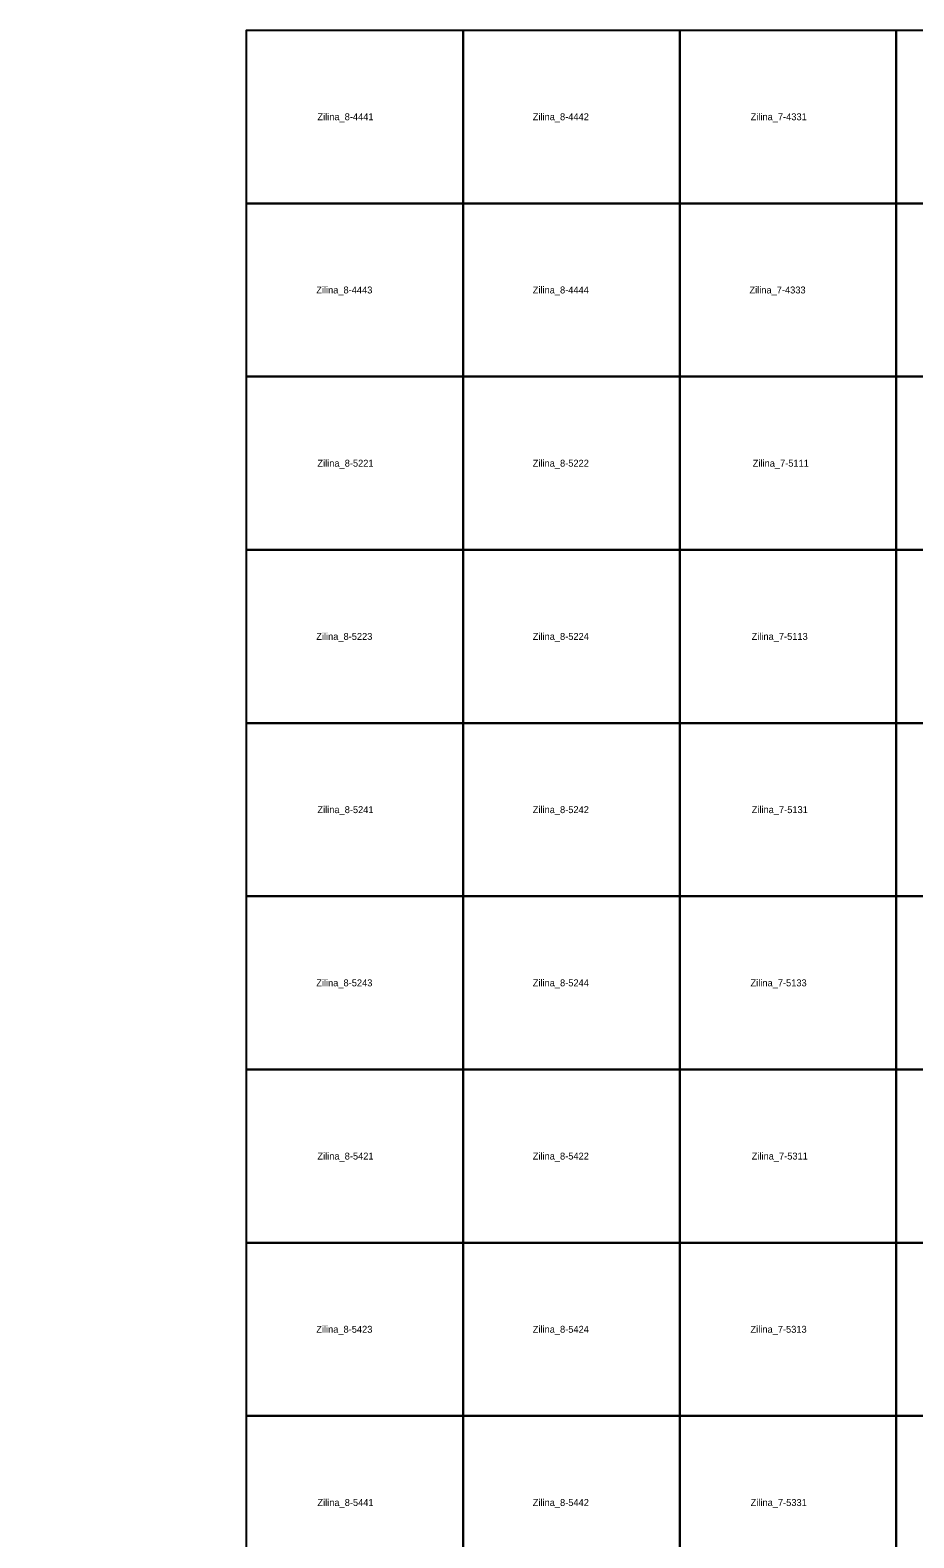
# Model space of a CAD drawing. Extents: x -445938 to -437812, y -1177250 to -1169500.
# Drawn here: x -445938 to -444662, y -1171676 to -1169500 of the extents above; entities that cross this region are included whole.
import ezdxf

# ---------------------------------------------------------------- set-up
doc = ezdxf.new("R2010")
doc.units = 0
for name, color, linetype in [('Vrstva 1', 7, 'Continuous'), ('Vrstva 4', 7, 'Continuous'), ('Vrstva 6', 7, 'Continuous')]:
    doc.layers.add(name, color=color, linetype=linetype)

msp = doc.modelspace()

# ---------------------------------------------------------------- linework, layer by layer
at = {"layer": 'Vrstva 1'}
msp.add_lwpolyline([(-440625, -1175500), (-441562.5, -1175500), (-441562.5, -1175000), (-442812.5, -1175000), (-442812.5, -1175750), (-443437.5, -1175750), (-443437.5, -1177250), (-445000, -1177250), (-445000, -1175500), (-445312.5, -1175500), (-445312.5, -1173750), (-445937.5, -1173750), (-445937.5, -1172250), (-445625, -1172250), (-445625, -1169500), (-444062.5, -1169500), (-444062.5, -1169750), (-441562.5, -1169750), (-441562.5, -1170000), (-440000, -1170000)], dxfattribs=at)
at = {"layer": 'Vrstva 4'}
for points in [[(-445312.5, -1169500), (-445312.5, -1169750), (-445625, -1169750), (-445625, -1169500)], [(-445000, -1169500), (-445000, -1169750), (-445312.5, -1169750), (-445312.5, -1169500)], [(-444687.5, -1169500), (-444687.5, -1169750), (-445000, -1169750), (-445000, -1169500)], [(-444375, -1169500), (-444375, -1169750), (-444687.5, -1169750), (-444687.5, -1169500)], [(-445312.5, -1169750), (-445312.5, -1170000), (-445625, -1170000), (-445625, -1169750)], [(-445000, -1169750), (-445000, -1170000), (-445312.5, -1170000), (-445312.5, -1169750)], [(-444687.5, -1169750), (-444687.5, -1170000), (-445000, -1170000), (-445000, -1169750)], [(-444375, -1169750), (-444375, -1170000), (-444687.5, -1170000), (-444687.5, -1169750)], [(-445312.5, -1170000), (-445312.5, -1170250), (-445625, -1170250), (-445625, -1170000)], [(-445000, -1170000), (-445000, -1170250), (-445312.5, -1170250), (-445312.5, -1170000)], [(-444687.5, -1170000), (-444687.5, -1170250), (-445000, -1170250), (-445000, -1170000)], [(-444375, -1170000), (-444375, -1170250), (-444687.5, -1170250), (-444687.5, -1170000)], [(-445312.5, -1170250), (-445312.5, -1170500), (-445625, -1170500), (-445625, -1170250)], [(-445000, -1170250), (-445000, -1170500), (-445312.5, -1170500), (-445312.5, -1170250)], [(-444687.5, -1170250), (-444687.5, -1170500), (-445000, -1170500), (-445000, -1170250)], [(-444375, -1170250), (-444375, -1170500), (-444687.5, -1170500), (-444687.5, -1170250)], [(-445312.5, -1170500), (-445312.5, -1170750), (-445625, -1170750), (-445625, -1170500)], [(-445000, -1170500), (-445000, -1170750), (-445312.5, -1170750), (-445312.5, -1170500)], [(-444687.5, -1170500), (-444687.5, -1170750), (-445000, -1170750), (-445000, -1170500)], [(-444375, -1170500), (-444375, -1170750), (-444687.5, -1170750), (-444687.5, -1170500)], [(-445312.5, -1170750), (-445312.5, -1171000), (-445625, -1171000), (-445625, -1170750)], [(-445000, -1170750), (-445000, -1171000), (-445312.5, -1171000), (-445312.5, -1170750)], [(-444687.5, -1170750), (-444687.5, -1171000), (-445000, -1171000), (-445000, -1170750)], [(-444375, -1170750), (-444375, -1171000), (-444687.5, -1171000), (-444687.5, -1170750)], [(-445312.5, -1171000), (-445312.5, -1171250), (-445625, -1171250), (-445625, -1171000)], [(-445000, -1171000), (-445000, -1171250), (-445312.5, -1171250), (-445312.5, -1171000)], [(-444687.5, -1171000), (-444687.5, -1171250), (-445000, -1171250), (-445000, -1171000)], [(-444375, -1171000), (-444375, -1171250), (-444687.5, -1171250), (-444687.5, -1171000)], [(-445312.5, -1171250), (-445312.5, -1171500), (-445625, -1171500), (-445625, -1171250)], [(-445000, -1171250), (-445000, -1171500), (-445312.5, -1171500), (-445312.5, -1171250)], [(-444687.5, -1171250), (-444687.5, -1171500), (-445000, -1171500), (-445000, -1171250)], [(-444375, -1171250), (-444375, -1171500), (-444687.5, -1171500), (-444687.5, -1171250)], [(-445312.5, -1171500), (-445312.5, -1171750), (-445625, -1171750), (-445625, -1171500)], [(-445000, -1171500), (-445000, -1171750), (-445312.5, -1171750), (-445312.5, -1171500)], [(-444687.5, -1171500), (-444687.5, -1171750), (-445000, -1171750), (-445000, -1171500)], [(-444375, -1171500), (-444375, -1171750), (-444687.5, -1171750), (-444687.5, -1171500)]]:
    msp.add_lwpolyline(points, close=True, dxfattribs=at)

# ---------------------------------------------------------------- texts
at = {"layer": 'Vrstva 6'}
for s, p in [('Zilina_8-4441', (-445522.878, -1169630)), ('Zilina_8-4442', (-445212.072, -1169630)), ('Zilina_7-4331', (-444897.564, -1169630)), ('Zilina_8-4443', (-445524.572, -1169880)), ('Zilina_8-4444', (-445212.072, -1169880)), ('Zilina_7-4333', (-444899.256, -1169880)), ('Zilina_8-5221', (-445522.878, -1170130)), ('Zilina_8-5222', (-445212.072, -1170130)), ('Zilina_7-5111', (-444894.494, -1170130)), ('Zilina_8-5223', (-445524.572, -1170380)), ('Zilina_8-5224', (-445212.072, -1170380)), ('Zilina_7-5113', (-444896.186, -1170380)), ('Zilina_8-5241', (-445522.878, -1170630)), ('Zilina_8-5242', (-445212.072, -1170630)), ('Zilina_7-5131', (-444896.028, -1170630)), ('Zilina_8-5243', (-445524.572, -1170880)), ('Zilina_8-5244', (-445212.072, -1170880)), ('Zilina_7-5133', (-444897.722, -1170880)), ('Zilina_8-5421', (-445522.878, -1171130)), ('Zilina_8-5422', (-445212.072, -1171130)), ('Zilina_7-5311', (-444896.028, -1171130)), ('Zilina_8-5423', (-445524.572, -1171380)), ('Zilina_8-5424', (-445212.072, -1171380)), ('Zilina_7-5313', (-444897.722, -1171380)), ('Zilina_8-5441', (-445522.878, -1171630)), ('Zilina_8-5442', (-445212.072, -1171630)), ('Zilina_7-5331', (-444897.564, -1171630))]:
    msp.add_text(s, height=10, dxfattribs=at).set_placement(p)

doc.saveas('drawing.dxf')
